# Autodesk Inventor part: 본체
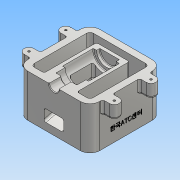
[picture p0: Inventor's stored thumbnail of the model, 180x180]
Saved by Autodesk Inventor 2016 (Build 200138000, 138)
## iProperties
Created: 2018-01
Part Number: 본체
Material: 알루미늄 6061
Document SubType Name: Modeling
Designer: Administrator
Mass: 994.396 g
Surface Area: 835.289 cm^2
Volume: 368.295 cm^3
Density: 2.7 g/cm^3
Appearance: 알루미늄 - 평지
Author: Administrator
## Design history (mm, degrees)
sketch "스케치1"
  geometry: L1 (-55, -55)-(55, -55); L2 (55, -55)-(55, 55); L3 (55, 55)-(-55, 55); L4 (-55, 55)-(-55, -55); L5 (-55, -55)-(55, 55); L6 (55, -55)-(-55, 55); 1 further point
  constraints: 12 end point, 2 midpoint, 2 parallel, 1 horizontal, 1 perpendicular
  dimensions: "d0" = 110 distance of L3.end L2.end; "d1" = 110 distance of L2.end L1.end
extrude "돌출1" new body sketch "스케치1" distance "d2" = 65; taper "d3" = 0 deg
sketch "스케치2"
  geometry: L1 (-55, -55)-(55, -55) reference; L2 (55, -55)-(55, 55) reference; L3 (55, 55)-(-55, 55) reference; L4 (-55, 55)-(-55, -55) reference; L5 (25, -55)-(25, 35); L6 (25, 35)-(-25, 35); L7 (-25, 35)-(-25, -55); L8 (-25, -55)-(-55, -55); L9 (-55, 55)-(55, 55); L10 (55, -55)-(55, 55); L11 (55, -55)-(25, -55); L12 (-55, -55)-(-55, 55); L13 (0, 55)-(0, -55); L14 (0, 45)-(-45, 45); L15 (-45, 45)-(-45, -45); L16 (-45, -45)-(-25, -45); L17 (25, -45)-(45, -45); L18 (45, -45)-(45, 45); L19 (45, 45)-(0, 45); 1 further point
  constraints: 30 end point, 6 perpendicular, 6 point on line, 2 collinear, 2 vertical, 1 horizontal, 1 midpoint, 1 parallel, 1 vertical alignment, 1 other
  dimensions: "d4" = 20 distance between parallel lines of L3 L6; "d5" = 50 distance between parallel lines of L5 L7; "d6" = 10 distance between parallel lines of L16 L8; "d7" = 10 distance between parallel lines of L15 L4; "d8" = 10 distance between parallel lines of L3 L14; "d9" = 10 distance between parallel lines of L2 L18
extrude "돌출2" cut sketch "스케치2" stored distance "d10" = 65; taper "d11" = 0 deg
sketch "스케치3"
  geometry: L1 (35, 65)-(35, 0) reference; L2 (-45, 0)-(35, 0) reference; L3 (35, 30)-(-45, 8.564); L4 (-45, 65)-(-45, 0) reference; 1 further point
  constraints: 2 end point, 2 point on line
  dimensions: "d12" = 30 distance from line of L2 L3.start; "d13" = 105 deg angle of L3 L4
extrude "돌출3" cut sketch "스케치3" stored distance "d14" = 65; taper "d15" = 0 deg
sketch "스케치4"
  geometry: L1 (-25, 35)-(-25, -45) reference; L2 (-55, -55)-(55, -55) reference; L3 (55, 55)-(-55, 55) reference; L4 (0, 55)-(0, -55); L5 (-7.5, -55)-(-7.5, -36); L6 (-7.5, -36)-(-16, -36); L7 (-16, -36)-(-16, -22); L8 (-16, -22)-(-20, -22); L9 (-20, -22)-(-20, 25); L10 (-20, 25)-(-15, 25); L11 (-15, 25)-(-15, 30); L12 (-15, 30)-(0, 30); 1 further point
  constraints: 18 end point, 7 perpendicular, 2 midpoint, 2 point on line, 1 vertical
  dimensions: "d16" = 30 diameter of L11 L4; "d17" = 32 diameter of L7 L4; "d18" = 40 diameter of L9 L4; "d19" = 15 diameter of L5 L4; "d20" = 19 distance of L5.start L5.end; "d21" = 14 distance of L6.end L7.end; "d22" = 47 distance of L8.end L9.end; "d23" = 5 distance of L10.end L11.end
revolve "회전1" sketch "스케치4" stored, may be unused: angle "d24" = 90 deg
node "작업 평면1"
sketch "스케치10"
  geometry: L1 (55, -55)-(55, 55) reference; L2 (-55, 55)-(-55, -55) reference; L3 (-55, -55)-(-7.5, -55) reference; L4 (-55, -35.5)-(-65, -35.5); L5 (-65, -35.5)-(-65, -20.5); L6 (-65, -20.5)-(-55, -20.5); L7 (-55, -20.5)-(-55, -35.5); L8 (-55, 20.5)-(-65, 20.5); L9 (-65, 20.5)-(-65, 35.5); L10 (-65, 35.5)-(-55, 35.5); L11 (-55, 35.5)-(-55, 20.5); L12 (-55, 0)-(55, 0); A1 r 7.5 centre (-65, -28) between (-65, -20.5) and (-65, -35.5); A2 r 7.5 centre (-65, 28) between (-65, 35.5) and (-65, 20.5); 1 further point
  constraints: 18 end point, 4 midpoint, 4 parallel, 4 point on circle, 2 centre point, 2 horizontal, 2 perpendicular, 2 point on line
  dimensions: "d44" = 10 distance of L5.end L6.end; "d46" = 7.5 radius of A1; "d47" = 27 distance from line of L3 A1.centre; "d48" = 10 distance of L9.end L10.end; "d49" = 7.5 radius of A2; "d50" = 56 distance of A2.centre A1.centre
extrude "돌출6" join sketch "스케치10" distance "d51" = 20; taper "d52" = 0 deg
hole "구멍1" diameter "d55" = 3.242; stored, may be unused: countersink angle "d59" = 90 deg, drill point angle "d61" = 118 deg; dims "d53" = 10, "d54" = 10, "d56" = 9, "d57" = 4, "d58" = 2, "d60" = 11
sketch "스케치11"
  geometry: L1 (0, 0)-(-65, 0) reference; L2 (0, 0)-(0, 110) reference; 2 further points
  constraints: 1 other
  dimensions: "d62" = 20 distance from line of L2 point (-20, 55); "d63" = 55 distance from line of L1 point (-20, 55)
feature "엠보싱1" sketch "스케치11" dims "d0" = 110, "d1" = 110, "d4" = 20, "d5" = 50, "d6" = 10, "d7" = 10, "d8" = 10, "d9" = 10, "d64" = 0.5, "d65" = 0
fillet "모깎기1" dims "d66" = 15
fillet "모깎기2" dims "d67" = 5
fillet "모깎기3" dims "d68" = 3
fillet "모깎기4" dims "d72" = 3
fillet "모깎기5" dims "d73" = 3
fillet "모깎기6" dims "d74" = 3
fillet "모깎기7" dims "d75" = 3
sketch "스케치12"
  geometry: L1 (-55, 11.061)-(15.681, 30); L2 (-42, 12.474)-(32, 32.302) reference; L3 (32.776, 29.404)-(-41.224, 9.576) reference; L4 (-45, 6.262)-(-45, 65) reference; L5 (-17, 39.243)-(-55, 29.061); L6 (-17, 39.243)-(15.681, 39.243); L7 (15.681, 39.243)-(15.681, 30); L8 (-21, 45)-(-21, 65) reference; L9 (-55, 29.061)-(-55, 11.061); L10 (-55, 0)-(-55, 65) reference; L11 (-22, 65)-(-22, 49) reference; L12 (40, 0)-(-40, 0) reference; 1 further point
  constraints: 10 end point, 1 collinear, 1 horizontal, 1 parallel, 1 perpendicular
  dimensions: "d76" = 5 distance between parallel lines of L3 L1; "d78" = 18 distance of L1.start L5.end; "d88" = 5 distance from line of L11 L5.start; "d89" = 30 distance from line of L12 L1.end; "d99" = 75 deg angle of L10 L5
extrude "돌출7" cut sketch "스케치12" stored distance "d81" = 30; taper "d82" = 0 deg
sketch "스케치13"
  geometry: L1 (15, 20)-(-15, 20); L2 (-15, 20)-(-15, -17); L3 (-15, -17)-(15, -17); L4 (15, -17)-(15, 20); L5 (-16, -22)-(16, -22) reference; 2 further points
  constraints: 8 end point, 2 parallel, 1 horizontal, 1 midpoint, 1 perpendicular, 1 vertical alignment
  dimensions: "d83" = 30 distance of L3.end L2.end; "d84" = 37 distance of L2.end L1.end; "d85" = 5 distance between parallel lines of L5 L3
extrude "돌출8" cut sketch "스케치13" distance "d86" = 35; taper "d87" = 0 deg
fillet "모깎기8" dims "d90" = 1
chamfer "모따기2" distance "d91" = 1; stored, may be unused: second distance "d92" = 2, angle "d93" = 45 deg
fillet "모깎기9" dims "d94" = 3
fillet "모깎기10" dims "d95" = 3
fillet "모깎기11" dims "d96" = 3
fillet "모깎기12" dims "d97" = 3
fillet "모깎기13" dims "d98" = 3
node "솔리드1"
mirror "대칭1"
mirror "대칭2"
mirror "대칭3"
